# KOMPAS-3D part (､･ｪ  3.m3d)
File: created 29.01.2016 13:47:21, last saved 25.07.2016 11:42:25.
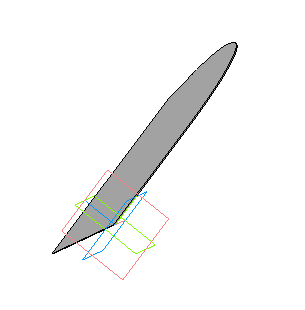
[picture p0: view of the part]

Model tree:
1. Эскиз:1
2. Операция выдавливания:1
     Толщина стенки 2 = 18; Расстояние 1 = 0.8
3. Эскиз:5
4. Вырезать элемент выдавливания:2
     Расстояние 1 = 10
5. Эскиз:6
6. Вырезать элемент выдавливания:3
     Расстояние 1 = 400
7. Эскиз:7
8. Вырезать элемент выдавливания:4
     Расстояние 2 = 400; Расстояние 1 = 400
